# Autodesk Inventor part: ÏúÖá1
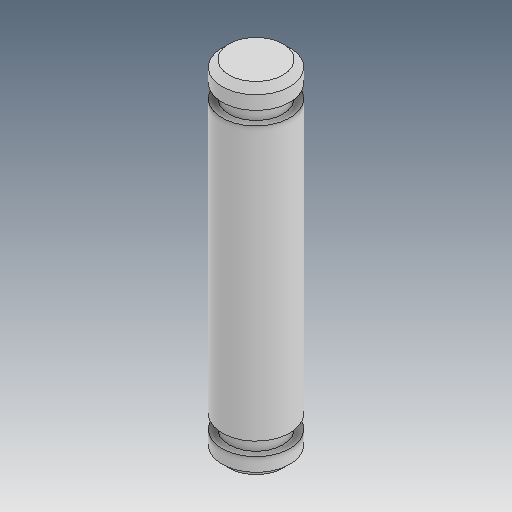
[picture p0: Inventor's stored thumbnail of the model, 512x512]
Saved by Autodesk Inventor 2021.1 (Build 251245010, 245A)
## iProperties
Created: 2013-04
Part Number: ÏúÖá1
Material: Ogólny
Document SubType Name: Modeling
Designer: user
Density: 1 g/cm^3
Appearance: Domyślna
Author: user
Revision Number: ÈÎºÎ
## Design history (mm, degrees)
feature "Ðý×ª1"
node "Bryła1"
